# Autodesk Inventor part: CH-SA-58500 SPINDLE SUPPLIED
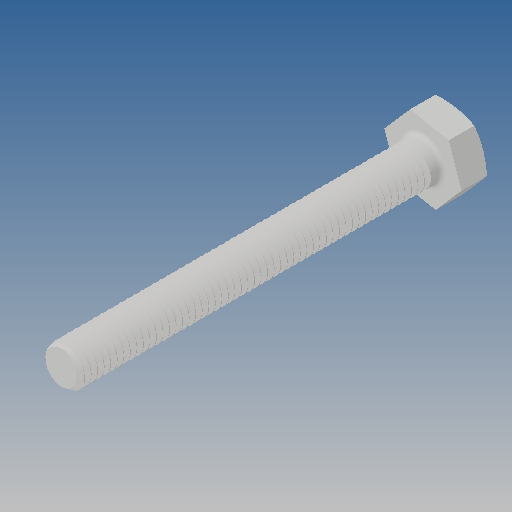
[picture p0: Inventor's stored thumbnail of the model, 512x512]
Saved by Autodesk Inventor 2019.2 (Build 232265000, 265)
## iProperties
Created: 2012-09
Part Number: CH-SA-58500 SPINDLE SUPPLIED
Material: Ogólny
Document SubType Name: Modeling
Designer: CADENGINEERING4
Density: 1 g/cm^3
Appearance: Domyślna
Author: CADENGINEERING4
Revision Number: ÈÎºÎ
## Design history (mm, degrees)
feature "ÇÐ³ý-É¨Ãè1"
node "Bryła1"
